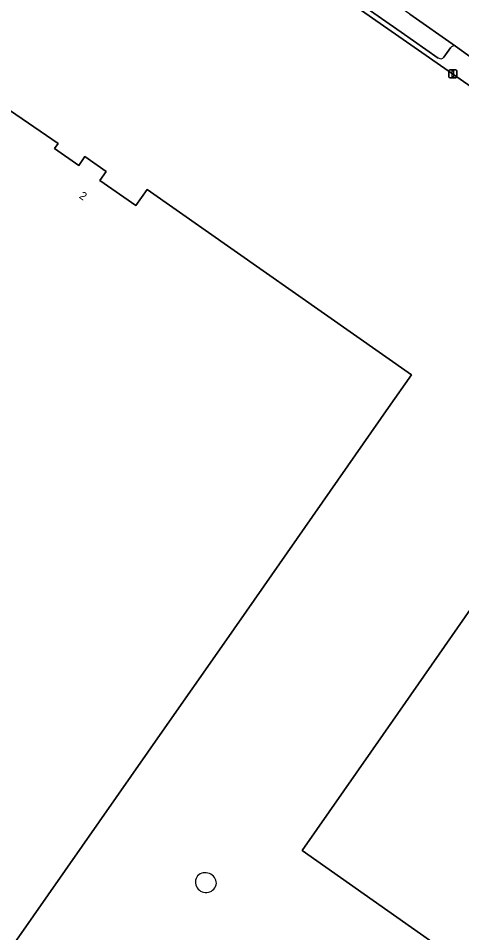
# Model space of a CAD drawing. Extents: x 155018 to 156648, y 383979 to 385733.
# Drawn here: x 155205.2 to 155260.7, y 385033.8 to 385148 of the extents above; entities that cross this region are included whole.
import ezdxf

# ---------------------------------------------------------------- set-up
doc = ezdxf.new("R2010")
doc.units = 0
for name, color, linetype in [('IMGEO_Erf', 7, 'Continuous'), ('IMGEO_Lichtmast', 7, 'Continuous'), ('IMGEO_Opslagtank', 7, 'Continuous'), ('IMGEO_Pand', 7, 'Continuous'), ('IMGEO_Pand_nummerreeks', 7, 'Continuous'), ('IMGEO_Parkeervlak_open', 7, 'Continuous'), ('IMGEO_Rijbaan_lokaal_gesloten', 7, 'Continuous'), ('IMGEO_Voetpad_open', 7, 'Continuous')]:
    doc.layers.add(name, color=color, linetype=linetype)

msp = doc.modelspace()

# ---------------------------------------------------------------- linework, layer by layer
at = {"layer": 'IMGEO_Erf'}
for points in [[(155421.75, 385027.62), (155395, 385046.28), (155391.03, 385049.05), (155385.59, 385052.84), (155385.4, 385052.96), (155380.15, 385056.63), (155341.35, 385083.76), (155335.66, 385087.64), (155324.96, 385095.15), (155317.04, 385100.72), (155292, 385118.3), (155289.29, 385120.2), (155288.53, 385120.61), (155288.14, 385120.83), (155288.02, 385120.66), (155281.33, 385125.34), (155281.52, 385125.64), (155276.13, 385129.55), (155243.35, 385152.36), (155212.56, 385173.84)], [(155201.16, 385138.56), (155210.21, 385132.38), (155209.76, 385131.74), (155212.78, 385129.64), (155213.55, 385130.75), (155216.21, 385128.89), (155215.43, 385127.77), (155219.94, 385124.63), (155221.35, 385126.65), (155254.39, 385103.49), (155251.52, 385099.4), (155233.76, 385073.98), (155230.66, 385069.55), (155223.54, 385059.39), (155202.84, 385029.83), (155219.21, 385018.36), (155206.36, 385000), (155188.01, 384973.8)], [(155279.93, 385016.52), (155240.71, 385044.07), (155252.68, 385061.18), (155267.91, 385083.02)]]:
    msp.add_lwpolyline(points, dxfattribs=at)
for centre, radius, start, end in [((155228.6, 385039.91), 1.4, 3.2005, 133.0451), ((155228.69, 385040.14), 1.31, 142.9034, 353.3422)]:
    msp.add_arc(centre, radius, start, end, dxfattribs=at)
at = {"layer": 'IMGEO_Lichtmast'}
for p, q in [((155259.07, 385140.68), (155259.07, 385141.48)), ((155259.07, 385141.48), (155259.07, 385140.68)), ((155259.17, 385141.58), (155259.96, 385141.58)), ((155259.96, 385141.58), (155259.17, 385141.58)), ((155260.06, 385141.48), (155260.06, 385140.68)), ((155260.06, 385140.68), (155260.06, 385141.48)), ((155259.96, 385140.58), (155259.17, 385140.58)), ((155259.17, 385140.58), (155259.96, 385140.58))]:
    msp.add_line(p, q, dxfattribs=at)
msp.add_lwpolyline([(155259.49, 385141.45), (155259.64, 385141.45), (155259.64, 385140.7), (155259.49, 385140.7), (155259.49, 385141.45)], dxfattribs=at)
for centre, start, end in [((155259.17, 385141.48), 90, 180), ((155259.17, 385141.48), 90, 180), ((155259.96, 385141.48), 0, 90), ((155259.96, 385141.48), 360, 90), ((155259.17, 385140.68), 180, 270), ((155259.17, 385140.68), 180, 270), ((155259.96, 385140.68), 270, 0), ((155259.96, 385140.68), 270, 0)]:
    msp.add_arc(centre, 0.1, start, end, dxfattribs=at)
at = {"layer": 'IMGEO_Opslagtank'}
for centre, radius, start, end in [((155228.6, 385039.91), 1.4, 3.2005, 133.0451), ((155228.69, 385040.14), 1.31, 142.9034, 353.3422)]:
    msp.add_arc(centre, radius, start, end, dxfattribs=at)
at = {"layer": 'IMGEO_Pand'}
for points in [[(155188.01, 384973.8), (155206.36, 385000), (155219.21, 385018.36), (155202.84, 385029.83), (155223.54, 385059.39), (155230.66, 385069.55), (155233.76, 385073.98), (155251.52, 385099.4), (155254.39, 385103.49), (155221.35, 385126.65), (155219.94, 385124.63), (155215.43, 385127.77), (155216.21, 385128.89), (155213.55, 385130.75), (155212.78, 385129.64), (155209.76, 385131.74), (155210.21, 385132.38), (155201.16, 385138.56)], [(155267.91, 385083.02), (155252.68, 385061.18), (155240.71, 385044.07), (155279.93, 385016.52)]]:
    msp.add_lwpolyline(points, dxfattribs=at)
at = {"layer": 'IMGEO_Parkeervlak_open'}
for points in [[(155259.89, 385144.52), (155254.18, 385148.52), (155246.01, 385154.33), (155229.43, 385165.92), (155218.39, 385173.57)], [(155217.67, 385171.03), (155244.9, 385152.04), (155253.12, 385146.29), (155257.74, 385143.06)], [(155258.44, 385143.15), (155259.27, 385144.32)]]:
    msp.add_lwpolyline(points, dxfattribs=at)
for centre, radius, start, end in [((155259.7, 385144.07), 0.493, 67.127, 148.6741), ((155258.05, 385143.48), 0.515, 233.3647, 320.4043)]:
    msp.add_arc(centre, radius, start, end, dxfattribs=at)
at = {"layer": 'IMGEO_Rijbaan_lokaal_gesloten'}
msp.add_lwpolyline([(155254.18, 385148.52), (155259.89, 385144.52), (155262.14, 385142.93), (155267.69, 385139.07), (155276.49, 385133.02), (155284.97, 385127.1), (155291.11, 385122.81), (155293.03, 385121.5), (155293.87, 385120.84), (155318.91, 385103.34), (155326.85, 385097.79), (155337.53, 385090.32), (155343.17, 385086.38), (155381.97, 385059.23), (155386.95, 385055.78), (155387.45, 385055.41), (155392.86, 385051.63), (155396.82, 385048.86), (155422.08, 385031.23)], dxfattribs=at)
at = {"layer": 'IMGEO_Voetpad_open'}
for points in [[(155212.56, 385173.84), (155243.35, 385152.36), (155276.13, 385129.55)], [(155257.74, 385143.06), (155253.12, 385146.29), (155244.9, 385152.04)], [(155259.27, 385144.32), (155258.44, 385143.15)], [(155262.14, 385142.93), (155259.89, 385144.52)]]:
    msp.add_lwpolyline(points, dxfattribs=at)
for centre, radius, start, end in [((155259.7, 385144.07), 0.493, 67.127, 148.6741), ((155258.05, 385143.48), 0.515, 233.3647, 320.4043)]:
    msp.add_arc(centre, radius, start, end, dxfattribs=at)

# ---------------------------------------------------------------- texts
at = {"layer": 'IMGEO_Pand_nummerreeks'}
msp.add_text('2', height=1, rotation=325.0725, dxfattribs=at).set_placement((155212.75, 385125.65))

doc.saveas('drawing.dxf')
